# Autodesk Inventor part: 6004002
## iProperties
Category: PARTsolutions
Created: 2007-09
Part Number: 6004002
Catalog Web Link: www.cadenas.de
Description: 6004002,6004002-M - Plunger
Document SubType Name: Modeling
Designer: PARTsolutions
Material: 1.0037 St 37-2
NB: 6004002
NN: 6004002,6004002-M
NT: Plunger
NBSYN: $MN.
LINA: 6004002
S: 6004
MN: 6004002
D: 0.50
D1: 0.19
L: 3.06
L1: 1.00
L2: 0.58
L3: 0.22
H1: 0.198
H2: 0.345
KDM: 0.2520
NDM: 0.3125
C: 0.02
NDM2: 0.000
KDM2: 0.000
C1: 0.000
L4: 0.000
KT: DUMMY
PSOL_IDENT_0: {\\partserver001.servicenet\dplatte\cadenas\23d-libs\destaco\industries\manual_clamps\straight_line_
PSOL_IDENT_1: action_clamps\through_hole_mount\6004_parts\6004_plunger.prj},158 {VTYP=3D},{NB=6004002},{LINA=60040
PSOL_IDENT_2: 02},{NN=6004002,6004002-M},{DATE=19.06.2006 12:13:07},{GEOMDATE=19.06.2006},{VERSION=},{LINEID=10},{
PSOL_IDENT_3: LINESUBID=-1},{WBVAR=}  {NB=6004002},{LINA=6004002},{KT=DUMMY},{S=6004},{MN=6004002},{D=0.50},{D1=0.
PSOL_IDENT_4: 19},{L=3.06},{L1=1.00},{L2=0.58},{L3=0.22},{H1=0.198},{H2=0.345},{KDM=0.2520},{NDM=0.3125},{C=0.02},
PSOL_IDENT_5: {NDM2=0.000},{KDM2=0.000},{C1=0.000},{L4=0.000}
Title: 6004002
Author: Cadenas PARTsolutions
Comments: Plunger
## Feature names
1. Revolution1
2. Extrusion1
3. Extrusion2
4. Bohrung1 [Hole]
